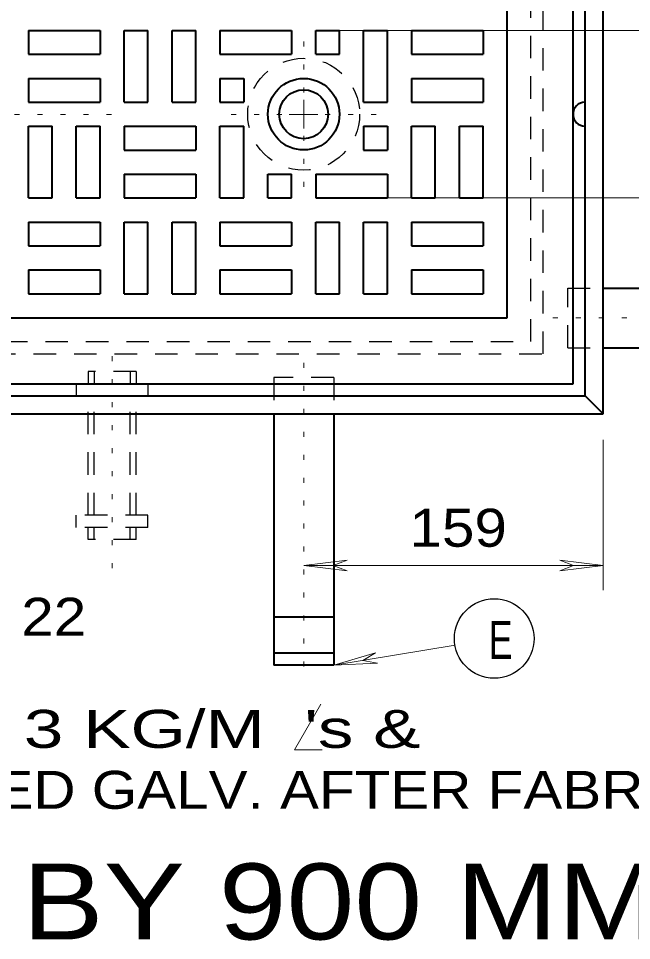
# Model space of a CAD drawing. Extents: x 312583 to 312854, y 144419 to 144597.
# Drawn here: x 312670.9 to 312683.17, y 144489.61 to 144508.06 of the extents above; entities that cross this region are included whole.
import ezdxf
from ezdxf.enums import TextEntityAlignment as Align

# ---------------------------------------------------------------- set-up
doc = ezdxf.new("R2010")
doc.units = 0
doc.header["$LTSCALE"] = 0.3
doc.linetypes.add('DOTTED', pattern=[1.5, 0.3, -1.2])
doc.linetypes.add('SHORT_DASHED', pattern=[2.7, 1.5, -1.2])
doc.layers.add('1', color=7, linetype='Continuous', lineweight=13)

msp = doc.modelspace()

# ---------------------------------------------------------------- linework, layer by layer
at = {"layer": '1', "lineweight": 40}
for p, q in [((312682.5955, 144500.1563), (312682.5955, 144512.1393)), ((312682.2351, 144500.5166), (312682.2351, 144511.779)), ((312681.9975, 144500.7543), (312681.9975, 144511.5413)), ((312680.6788, 144502.073), (312680.6788, 144510.2226)), ((312671.0955, 144507.823), (312672.5291, 144507.823)), ((312671.0955, 144507.823), (312671.0955, 144507.3476)), ((312672.5291, 144507.823), (312672.5291, 144507.3476)), ((312673.0121, 144506.3893), (312673.0121, 144507.823)), ((312673.0121, 144507.823), (312673.4875, 144507.823)), ((312673.4875, 144506.3893), (312673.4875, 144507.823)), ((312673.9705, 144506.3893), (312673.9705, 144507.823)), ((312673.9705, 144507.823), (312674.4458, 144507.823)), ((312674.4458, 144506.3893), (312674.4458, 144507.823)), ((312674.9288, 144507.823), (312676.3625, 144507.823)), ((312674.9288, 144507.823), (312674.9288, 144507.3476)), ((312676.3625, 144507.823), (312676.3625, 144507.3476)), ((312676.8455, 144507.3476), (312676.8455, 144507.823)), ((312676.8455, 144507.823), (312677.3208, 144507.823)), ((312677.3208, 144507.3476), (312677.3208, 144507.823)), ((312677.8038, 144506.3893), (312677.8038, 144507.823)), ((312677.8038, 144507.823), (312678.2791, 144507.823)), ((312678.2791, 144506.3893), (312678.2791, 144507.823)), ((312678.7621, 144507.823), (312680.1958, 144507.823)), ((312678.7621, 144507.823), (312678.7621, 144507.3476)), ((312680.1958, 144507.823), (312680.1958, 144507.3476)), ((312671.0955, 144507.3476), (312672.5291, 144507.3476)), ((312674.9288, 144507.3476), (312676.3625, 144507.3476)), ((312676.8455, 144507.3476), (312677.3208, 144507.3476)), ((312678.7621, 144507.3476), (312680.1958, 144507.3476)), ((312671.0955, 144506.8646), (312672.5291, 144506.8646)), ((312671.0955, 144506.8646), (312671.0955, 144506.3893)), ((312672.5291, 144506.8646), (312672.5291, 144506.3893)), ((312674.9288, 144506.8646), (312675.4041, 144506.8646)), ((312674.9288, 144506.8646), (312674.9288, 144506.3893)), ((312675.4041, 144506.8646), (312675.4041, 144506.3893)), ((312678.7621, 144506.8646), (312680.1958, 144506.8646)), ((312678.7621, 144506.8646), (312678.7621, 144506.3893)), ((312680.1958, 144506.8646), (312680.1958, 144506.3893)), ((312671.0955, 144506.3893), (312672.5291, 144506.3893)), ((312673.0121, 144506.3893), (312673.4875, 144506.3893)), ((312673.9705, 144506.3893), (312674.4458, 144506.3893)), ((312674.9288, 144506.3893), (312675.4041, 144506.3893)), ((312677.8038, 144506.3893), (312678.2791, 144506.3893)), ((312678.7621, 144506.3893), (312680.1958, 144506.3893)), ((312671.0955, 144504.4726), (312671.0955, 144505.9063)), ((312671.0955, 144505.9063), (312671.5708, 144505.9063)), ((312671.5708, 144504.4726), (312671.5708, 144505.9063)), ((312672.0538, 144504.4726), (312672.0538, 144505.9063)), ((312672.0538, 144505.9063), (312672.5291, 144505.9063)), ((312672.5291, 144504.4726), (312672.5291, 144505.9063)), ((312673.0121, 144505.9063), (312674.4458, 144505.9063)), ((312673.0121, 144505.9063), (312673.0121, 144505.431)), ((312674.4458, 144505.9063), (312674.4458, 144505.431)), ((312674.9288, 144504.4726), (312674.9288, 144505.9063)), ((312674.9288, 144505.9063), (312675.4041, 144505.9063)), ((312675.4041, 144504.4726), (312675.4041, 144505.9063)), ((312677.8038, 144505.9063), (312678.2791, 144505.9063)), ((312677.8038, 144505.9063), (312677.8038, 144505.431)), ((312678.2791, 144505.9063), (312678.2791, 144505.431)), ((312678.7621, 144504.4726), (312678.7621, 144505.9063)), ((312678.7621, 144505.9063), (312679.2375, 144505.9063)), ((312679.2375, 144504.4726), (312679.2375, 144505.9063)), ((312679.7205, 144504.4726), (312679.7205, 144505.9063)), ((312679.7205, 144505.9063), (312680.1958, 144505.9063)), ((312680.1958, 144504.4726), (312680.1958, 144505.9063)), ((312673.0121, 144505.431), (312674.4458, 144505.431)), ((312677.8038, 144505.431), (312678.2791, 144505.431)), ((312673.0121, 144504.948), (312674.4458, 144504.948)), ((312673.0121, 144504.948), (312673.0121, 144504.4726)), ((312674.4458, 144504.948), (312674.4458, 144504.4726)), ((312675.8871, 144504.4726), (312675.8871, 144504.948)), ((312675.8871, 144504.948), (312676.3625, 144504.948)), ((312676.3625, 144504.4726), (312676.3625, 144504.948)), ((312676.8455, 144504.948), (312678.2791, 144504.948)), ((312676.8455, 144504.948), (312676.8455, 144504.4726)), ((312678.2791, 144504.948), (312678.2791, 144504.4726)), ((312671.0955, 144504.4726), (312671.5708, 144504.4726)), ((312672.0538, 144504.4726), (312672.5291, 144504.4726)), ((312673.0121, 144504.4726), (312674.4458, 144504.4726)), ((312674.9288, 144504.4726), (312675.4041, 144504.4726)), ((312675.8871, 144504.4726), (312676.3625, 144504.4726)), ((312676.8455, 144504.4726), (312678.2791, 144504.4726)), ((312678.7621, 144504.4726), (312679.2375, 144504.4726)), ((312679.7205, 144504.4726), (312680.1958, 144504.4726)), ((312671.0955, 144503.9896), (312672.5291, 144503.9896)), ((312671.0955, 144503.9896), (312671.0955, 144503.5143)), ((312672.5291, 144503.9896), (312672.5291, 144503.5143)), ((312673.0121, 144502.556), (312673.0121, 144503.9896)), ((312673.0121, 144503.9896), (312673.4875, 144503.9896)), ((312673.4875, 144502.556), (312673.4875, 144503.9896)), ((312673.9705, 144502.556), (312673.9705, 144503.9896)), ((312673.9705, 144503.9896), (312674.4458, 144503.9896)), ((312674.4458, 144502.556), (312674.4458, 144503.9896)), ((312674.9288, 144503.9896), (312676.3625, 144503.9896)), ((312674.9288, 144503.9896), (312674.9288, 144503.5143)), ((312676.3625, 144503.9896), (312676.3625, 144503.5143)), ((312676.8455, 144502.556), (312676.8455, 144503.9896)), ((312676.8455, 144503.9896), (312677.3208, 144503.9896)), ((312677.3208, 144502.556), (312677.3208, 144503.9896)), ((312677.8038, 144502.556), (312677.8038, 144503.9896)), ((312677.8038, 144503.9896), (312678.2791, 144503.9896)), ((312678.2791, 144502.556), (312678.2791, 144503.9896)), ((312678.7621, 144503.9896), (312680.1958, 144503.9896)), ((312678.7621, 144503.9896), (312678.7621, 144503.5143)), ((312680.1958, 144503.9896), (312680.1958, 144503.5143)), ((312671.0955, 144503.5143), (312672.5291, 144503.5143)), ((312674.9288, 144503.5143), (312676.3625, 144503.5143)), ((312678.7621, 144503.5143), (312680.1958, 144503.5143)), ((312671.0955, 144503.0313), (312672.5291, 144503.0313)), ((312671.0955, 144503.0313), (312671.0955, 144502.556)), ((312672.5291, 144503.0313), (312672.5291, 144502.556)), ((312674.9288, 144503.0313), (312676.3625, 144503.0313)), ((312674.9288, 144503.0313), (312674.9288, 144502.556)), ((312676.3625, 144503.0313), (312676.3625, 144502.556)), ((312678.7621, 144503.0313), (312680.1958, 144503.0313)), ((312678.7621, 144503.0313), (312678.7621, 144502.556)), ((312680.1958, 144503.0313), (312680.1958, 144502.556)), ((312671.0955, 144502.556), (312672.5291, 144502.556)), ((312673.0121, 144502.556), (312673.4875, 144502.556)), ((312673.9705, 144502.556), (312674.4458, 144502.556)), ((312674.9288, 144502.556), (312676.3625, 144502.556)), ((312676.8455, 144502.556), (312677.3208, 144502.556)), ((312677.8038, 144502.556), (312678.2791, 144502.556)), ((312678.7621, 144502.556), (312680.1958, 144502.556)), ((312682.6108, 144502.671), (312687.6401, 144502.671)), ((312647.6125, 144502.073), (312680.6788, 144502.073)), ((312682.6108, 144501.475), (312687.6401, 144501.475)), ((312646.3015, 144500.7543), (312681.9975, 144500.7543)), ((312646.0561, 144500.5166), (312682.2351, 144500.5166)), ((312682.2351, 144500.5166), (312682.5955, 144500.1563)), ((312645.6958, 144500.1563), (312682.5955, 144500.1563)), ((312676.0098, 144500.1563), (312676.0098, 144495.127)), ((312677.2058, 144500.1563), (312677.2058, 144495.127)), ((312677.2058, 144496.0853), (312676.0098, 144496.0853)), ((312677.2058, 144495.3646), (312676.0098, 144495.3646)), ((312677.2058, 144495.127), (312676.0098, 144495.127))]:
    msp.add_line(p, q, dxfattribs=at)
at = {"layer": '1', "linetype": 'SHORT_DASHED', "lineweight": 25}
for p, q in [((312681.3995, 144501.3523), (312681.3995, 144510.9356)), ((312681.1541, 144501.5976), (312681.1541, 144510.698)), ((312681.8901, 144501.475), (312681.8901, 144502.671)), ((312681.8901, 144502.671), (312682.6108, 144502.671)), ((312647.1371, 144501.5976), (312681.1541, 144501.5976)), ((312681.8901, 144501.475), (312682.6108, 144501.475)), ((312646.8995, 144501.3523), (312681.3995, 144501.3523)), ((312673.2498, 144500.9996), (312672.2915, 144500.9996)), ((312672.2915, 144500.9996), (312672.2915, 144500.7543)), ((312672.4141, 144500.9996), (312672.4141, 144500.7543)), ((312673.1348, 144500.9996), (312673.1348, 144500.7543)), ((312673.2498, 144500.9996), (312673.2498, 144500.7543)), ((312677.2058, 144500.877), (312676.0098, 144500.877)), ((312676.0098, 144500.877), (312676.0098, 144500.1563)), ((312677.2058, 144500.877), (312677.2058, 144500.1563)), ((312673.4875, 144500.7543), (312672.0538, 144500.7543)), ((312672.0538, 144500.7543), (312672.0538, 144500.5166)), ((312673.4875, 144500.7543), (312673.4875, 144500.5166)), ((312672.2915, 144498.1246), (312672.2915, 144500.5166)), ((312672.4141, 144498.1246), (312672.4141, 144500.5166)), ((312673.1348, 144498.1246), (312673.1348, 144500.5166)), ((312673.2498, 144498.1246), (312673.2498, 144500.5166)), ((312673.4875, 144498.1246), (312672.0538, 144498.1246)), ((312672.0538, 144497.8793), (312672.0538, 144498.1246)), ((312673.4875, 144497.8793), (312673.4875, 144498.1246)), ((312673.4875, 144497.8793), (312672.0538, 144497.8793)), ((312672.2915, 144497.6416), (312672.2915, 144497.8793)), ((312672.4141, 144497.6416), (312672.4141, 144497.8793)), ((312673.1348, 144497.6416), (312673.1348, 144497.8793)), ((312673.2498, 144497.6416), (312673.2498, 144497.8793)), ((312673.2498, 144497.6416), (312672.2915, 144497.6416))]:
    msp.add_line(p, q, dxfattribs=at)
at = {"layer": '1', "linetype": 'DOTTED'}
for p, q in [((312676.6078, 144506.581), (312676.6078, 144507.6926)), ((312665.2995, 144506.144), (312672.9661, 144506.144)), ((312676.1708, 144506.144), (312675.0361, 144506.144)), ((312677.0371, 144506.144), (312678.1335, 144506.144)), ((312676.6078, 144505.7146), (312676.6078, 144504.557)), ((312681.5911, 144502.073), (312687.9851, 144502.073)), ((312672.7745, 144497.0666), (312672.7745, 144501.5516)), ((312676.6078, 144501.176), (312676.6078, 144494.7743))]:
    msp.add_line(p, q, dxfattribs=at)
at = {"layer": '1'}
for p, q in [((312677.3208, 144507.823), (312686.5515, 144507.823)), ((312676.6078, 144506.144), (312676.6078, 144506.4353)), ((312676.6078, 144506.144), (312676.3165, 144506.144)), ((312676.6078, 144506.144), (312676.8915, 144506.144)), ((312676.6078, 144506.144), (312676.6078, 144505.8603)), ((312677.3208, 144504.4726), (312686.5515, 144504.4726)), ((312682.5955, 144499.635), (312682.5955, 144496.622)), ((312676.6078, 144497.1203), (312677.4741, 144497.2276)), ((312677.4741, 144497.2276), (312677.1981, 144497.1203)), ((312681.7291, 144497.2276), (312682.0051, 144497.1203)), ((312682.5955, 144497.1203), (312681.7291, 144497.2276)), ((312682.5955, 144497.1203), (312676.6078, 144497.1203)), ((312676.6078, 144497.1203), (312677.4741, 144497.013)), ((312677.4741, 144497.013), (312677.1981, 144497.1203)), ((312681.7291, 144497.013), (312682.0051, 144497.1203)), ((312682.5955, 144497.1203), (312681.7291, 144497.013)), ((312679.6361, 144495.5256), (312677.2058, 144495.127)), ((312677.2058, 144495.127), (312678.0415, 144495.3723)), ((312678.0415, 144495.3723), (312677.7885, 144495.219)), ((312677.2058, 144495.127), (312678.0798, 144495.1653)), ((312678.0798, 144495.1653), (312677.7885, 144495.219))]:
    msp.add_line(p, q, dxfattribs=at)
msp.add_lwpolyline([(312676.9502, 144494.344), (312676.4212, 144493.4317), (312676.9732, 144493.4317)], dxfattribs=at)
at = {"layer": '1', "linetype": 'SHORT_DASHED', "lineweight": 25}
msp.add_circle((312676.6049, 144506.1478), 1.1201, dxfattribs=at)
at = {"layer": '1', "lineweight": 40}
for radius in [0.7155, 0.4899]:
    msp.add_circle((312676.6049, 144506.1478), radius, dxfattribs=at)
at = {"layer": '1', "lineweight": 25}
msp.add_circle((312680.4181, 144495.6579), 0.7964, dxfattribs=at)
at = {"layer": '1', "lineweight": 40}
msp.add_arc((312682.2351, 144506.1478), 0.2396, 90, 270, dxfattribs=at)

# ---------------------------------------------------------------- texts
at = {"layer": '1'}
for s, width, p in [('159 ', 1.15, (312678.7219, 144497.4942)), ('22 ', 1.15, (312670.9532, 144495.7134)), ('E', 0.7, (312680.3107, 144495.2506)), ("30 BY 30 BY 6 MM  's @ 3 KG/M  's &", 1.4, (312654.8958, 144493.47)), ('ANCHORS TO BE HOT DIPPED GALV. AFTER FABRICATION', 1.15, (312654.8958, 144492.25))]:
    msp.add_text(s, height=0.76, dxfattribs=dict(at, width=width)).set_placement(p)
at = {"layer": '1', "width": 1.2}
msp.add_text('PLAN-FRAME AND COVER FOR 250 BY 900 MM JUNCTION BOX', height=1.52, dxfattribs=at).set_placement((312665.6882, 144489.6359), align=Align.CENTER)

doc.saveas('drawing.dxf')
